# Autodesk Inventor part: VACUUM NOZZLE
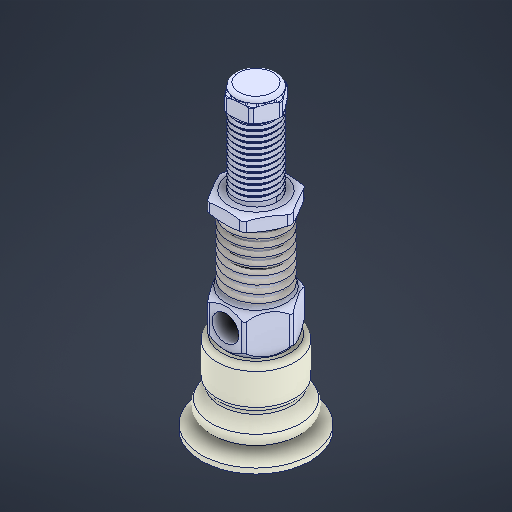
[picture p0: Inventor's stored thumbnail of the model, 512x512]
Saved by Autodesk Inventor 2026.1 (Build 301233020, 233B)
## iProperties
Created: 2025-01
Part Number: VACUUM NOZZLE
Material: Generic
Document SubType Name: Modeling
Designer: hp
Density: 1 g/cm^3
Appearance: Default
Author: hp
Sending System: SOLIDWORKS 2025
Last Saved Date: 2026-02-26
last saved by: liban
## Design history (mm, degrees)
feature "Cut-Extrude2"
node "Plane1"
body "Solid1"
